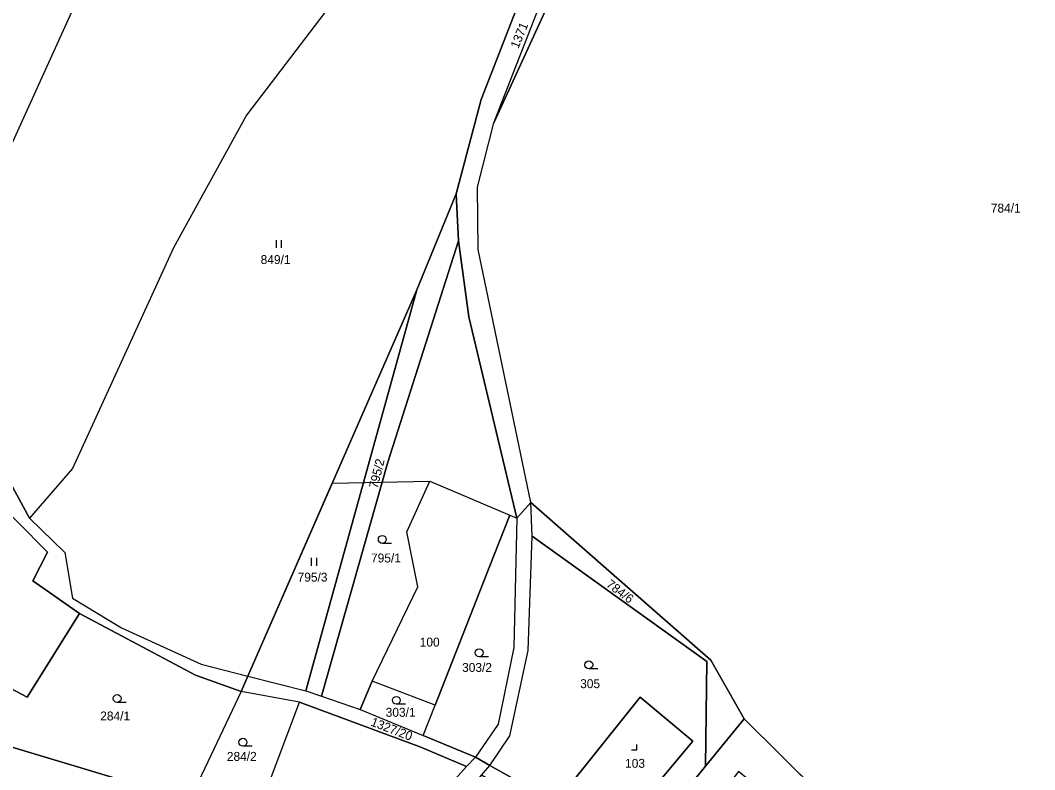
# Model space of a CAD drawing. Extents: x -588699 to -585793, y -1060280 to -1056731.
# Drawn here: x -587576 to -587382.9, y -1058239.7 to -1058097.1 of the extents above; entities that cross this region are included whole.
import ezdxf

# ---------------------------------------------------------------- set-up
doc = ezdxf.new("R2010")
doc.units = 0
for name, color, linetype in [('Druh pozemku', 7, 'Continuous'), ('Lesy', 7, 'Continuous'), ('Parcela nároku', 7, 'Continuous'), ('Vnější obvod_k šeření', 7, 'Continuous')]:
    doc.layers.add(name, color=color, linetype=linetype)

msp = doc.modelspace()

# ---------------------------------------------------------------- linework, layer by layer
at = {"layer": 'Druh pozemku'}
for p, q in [((-587527.32, -1058138.93), (-587527.32, -1058140.43)), ((-587526.3, -1058140.43), (-587526.3, -1058138.93)), ((-587505.34, -1058196.66), (-587507.09, -1058196.66)), ((-587520.6, -1058199.42), (-587520.6, -1058200.92)), ((-587519.58, -1058200.92), (-587519.58, -1058199.42)), ((-587486.89, -1058218.23), (-587488.64, -1058218.23)), ((-587466.02, -1058220.53), (-587467.77, -1058220.53)), ((-587555.83, -1058226.93), (-587557.58, -1058226.93)), ((-587502.67, -1058227.28), (-587504.42, -1058227.28)), ((-587531.88, -1058235.26), (-587533.63, -1058235.26))]:
    msp.add_line(p, q, dxfattribs=at)
msp.add_lwpolyline([(-587459.64, -1058235.92), (-587458.64, -1058235.92), (-587458.64, -1058234.92)], dxfattribs=at)
for centre in [(-587507.09, -1058195.91), (-587488.64, -1058217.48), (-587467.77, -1058219.78), (-587557.58, -1058226.18), (-587504.42, -1058226.53), (-587533.63, -1058234.51)]:
    msp.add_circle(centre, 0.75, dxfattribs=at)
at = {"layer": 'Lesy'}
for p, q in [((-587532.69, -1058221.91), (-587516.61, -1058185.17)), ((-587516.61, -1058185.17), (-587498.02, -1058184.82)), ((-587516.61, -1058185.17), (-587516.61, -1058185.17)), ((-587516.61, -1058185.17), (-587516.61, -1058185.17)), ((-587498.02, -1058184.82), (-587482.8, -1058191.31)), ((-587481.48, -1058191.87), (-587478.83, -1058188.89)), ((-587478.83, -1058188.89), (-587444.54, -1058218.88)), ((-587482.8, -1058191.31), (-587481.48, -1058191.87)), ((-587576.63, -1058192.51), (-587570.81, -1058198.31)), ((-587570.81, -1058198.31), (-587573.61, -1058203.8)), ((-587573.61, -1058203.8), (-587564.72, -1058210.02)), ((-587564.72, -1058210.02), (-587542.68, -1058221.73)), ((-587444.54, -1058218.88), (-587438.17, -1058230.02)), ((-587542.68, -1058221.73), (-587533.98, -1058224.84)), ((-587533.98, -1058224.84), (-587532.69, -1058221.91)), ((-587438.17, -1058230.02), (-587409.09, -1058258.83))]:
    msp.add_line(p, q, dxfattribs=at)
at = {"layer": 'Parcela nároku'}
for points in [[(-587527.58, -1058033.11), (-587512.43, -1058021.56), (-587484.15, -1058010.09), (-587474.8, -1058004.29), (-587465.82, -1058059.86), (-587503.14, -1058076.04), (-587532.94, -1058115.16), (-587546.85, -1058140.39), (-587566.06, -1058182.4), (-587574.29, -1058191.87), (-587590.81, -1058161.45), (-587593.08, -1058145.43), (-587589.69, -1058125.26), (-587570.64, -1058078.67), (-587551.05, -1058065.74), (-587538.76, -1058045.77)], [(-587345.44, -1058028.92), (-587320.47, -1058029.95), (-587326.37, -1058086.73), (-587339.42, -1058135.2), (-587351.4, -1058206.3), (-587377.92, -1058277.75), (-587409.09, -1058258.83), (-587438.17, -1058230.02), (-587444.54, -1058218.88), (-587478.83, -1058188.89), (-587488.81, -1058140.74), (-587488.94, -1058128.88), (-587485.87, -1058116.62), (-587469.24, -1058080.38), (-587460.27, -1058069.38), (-587445.31, -1058054.69), (-587393.66, -1058044.61), (-587379.52, -1058038.97), (-587353.28, -1058031.95)], [(-587472.47, -1058082.32), (-587463.05, -1058066.61), (-587456.91, -1058059.97), (-587445.31, -1058054.69), (-587460.27, -1058069.38), (-587469.24, -1058080.38), (-587485.87, -1058116.62)], [(-587546.85, -1058140.39), (-587566.06, -1058182.4), (-587574.29, -1058191.87), (-587567.55, -1058198.39), (-587566.06, -1058207.06), (-587556.73, -1058212.76), (-587541.57, -1058219.62), (-587532.69, -1058221.91), (-587500.54, -1058148.42), (-587493.05, -1058130.11), (-587488.27, -1058112.18), (-587475.92, -1058080.51), (-587464.99, -1058063.65), (-587465.82, -1058059.86), (-587503.14, -1058076.04), (-587532.94, -1058115.16)], [(-587488.27, -1058112.18), (-587493.05, -1058130.11), (-587492.55, -1058139.05), (-587490.61, -1058153.54), (-587481.48, -1058191.87), (-587482.06, -1058216.46), (-587485.02, -1058231.04), (-587489.32, -1058237.37), (-587486.6, -1058238.91), (-587482.8, -1058233.27), (-587479.34, -1058217.02), (-587478.55, -1058195.26), (-587478.83, -1058188.89), (-587488.81, -1058140.74), (-587488.94, -1058128.88), (-587485.87, -1058116.62), (-587472.47, -1058082.32), (-587463.05, -1058066.61), (-587456.91, -1058059.97), (-587464.99, -1058063.65), (-587475.92, -1058080.51)], [(-587493.05, -1058130.11), (-587500.54, -1058148.42), (-587521.67, -1058224.75), (-587518.67, -1058225.76), (-587506.06, -1058181.19), (-587492.55, -1058139.05)], [(-587490.61, -1058153.54), (-587492.55, -1058139.05), (-587506.06, -1058181.19), (-587518.67, -1058225.76), (-587511.28, -1058228.3), (-587509.02, -1058222.9), (-587500.32, -1058204.9), (-587502.39, -1058194.46), (-587498.02, -1058184.82), (-587482.8, -1058191.31), (-587481.48, -1058191.87)], [(-587500.54, -1058148.42), (-587532.69, -1058221.91), (-587521.67, -1058224.75)], [(-587613.49, -1058209.28), (-587594.49, -1058181.8), (-587592.95, -1058183.93), (-587589.15, -1058186.74), (-587582.84, -1058191.41), (-587580.71, -1058188.44), (-587576.63, -1058192.51), (-587570.81, -1058198.31), (-587573.61, -1058203.8), (-587564.72, -1058210.02), (-587574.71, -1058225.95), (-587584.71, -1058220.65), (-587580.51, -1058214.58), (-587588.96, -1058208.27), (-587593.11, -1058213.84), (-587596.84, -1058210.95), (-587597.22, -1058210.65), (-587606.24, -1058203.65)], [(-587498.02, -1058184.82), (-587482.8, -1058191.31), (-587486.72, -1058201.25), (-587489.71, -1058208.84), (-587497.04, -1058227.45), (-587509.02, -1058222.9), (-587500.32, -1058204.9), (-587502.39, -1058194.46)], [(-587445.52, -1058239.05), (-587445.31, -1058219.16), (-587478.55, -1058195.26), (-587478.83, -1058188.89), (-587444.54, -1058218.88), (-587438.17, -1058230.02)], [(-587489.71, -1058208.84), (-587486.72, -1058201.25), (-587482.8, -1058191.31), (-587481.48, -1058191.87), (-587482.06, -1058216.46), (-587485.02, -1058231.04), (-587489.32, -1058237.37), (-587499.32, -1058233.23), (-587497.04, -1058227.45)], [(-587486.6, -1058238.91), (-587482.8, -1058233.27), (-587479.34, -1058217.02), (-587478.55, -1058195.26), (-587445.31, -1058219.16), (-587445.52, -1058239.05), (-587458.33, -1058254.77)], [(-587564.72, -1058210.02), (-587542.68, -1058221.73), (-587533.98, -1058224.84), (-587543.81, -1058245.62), (-587594.11, -1058230.47), (-587604.18, -1058226.81), (-587600.44, -1058221.67), (-587594.99, -1058216.36), (-587586.42, -1058223.13), (-587584.71, -1058220.65), (-587574.71, -1058225.95)], [(-587499.32, -1058233.23), (-587489.32, -1058237.37), (-587491.04, -1058239.13), (-587499.77, -1058235.44), (-587522.86, -1058226.86), (-587533.98, -1058224.84), (-587532.69, -1058221.91), (-587521.67, -1058224.75), (-587518.67, -1058225.76), (-587511.28, -1058228.3)], [(-587509.02, -1058222.9), (-587511.28, -1058228.3), (-587499.32, -1058233.23), (-587497.04, -1058227.45)], [(-587522.86, -1058226.86), (-587533.98, -1058224.84), (-587543.81, -1058245.62), (-587531.58, -1058249.98)], [(-587457.98, -1058225.94), (-587470.2, -1058241.13), (-587459.27, -1058251.43), (-587454.05, -1058245.1), (-587455.68, -1058243.56), (-587447.93, -1058234.31)], [(-587447.93, -1058234.31), (-587455.68, -1058243.56), (-587454.05, -1058245.1), (-587459.27, -1058251.43), (-587470.2, -1058241.13), (-587457.98, -1058225.94)], [(-587522.86, -1058226.86), (-587499.77, -1058235.44), (-587491.04, -1058239.13), (-587511.42, -1058261.89), (-587520.95, -1058253.77), (-587531.58, -1058249.98)], [(-587438.17, -1058230.02), (-587409.09, -1058258.83), (-587377.92, -1058277.75), (-587379.39, -1058282.93), (-587379.69, -1058284.16), (-587380.64, -1058288.11), (-587382.51, -1058301.76), (-587401.12, -1058288.15), (-587430.44, -1058266.69), (-587421.74, -1058254.37), (-587439.28, -1058240.07), (-587475.39, -1058286.82), (-587481.24, -1058282.88), (-587459.91, -1058256.7), (-587458.33, -1058254.77), (-587445.52, -1058239.05)], [(-587491.04, -1058239.13), (-587511.42, -1058261.89), (-587508.12, -1058264.7), (-587488.17, -1058240.8), (-587486.6, -1058238.91), (-587489.32, -1058237.37)], [(-587486.6, -1058238.91), (-587458.33, -1058254.77), (-587459.91, -1058256.7), (-587464.95, -1058253.95), (-587474.34, -1058248.83), (-587488.17, -1058240.8)]]:
    msp.add_lwpolyline(points, close=True, dxfattribs=at)
for points in [[(-587590.81, -1058161.45), (-587574.29, -1058191.87), (-587567.55, -1058198.39), (-587566.06, -1058207.06), (-587556.73, -1058212.76), (-587541.57, -1058219.62), (-587532.69, -1058221.91), (-587533.98, -1058224.84), (-587542.68, -1058221.73), (-587564.72, -1058210.02), (-587573.61, -1058203.8), (-587570.81, -1058198.31), (-587576.63, -1058192.51)], [(-587594.11, -1058230.47), (-587543.81, -1058245.62), (-587531.58, -1058249.98), (-587520.95, -1058253.77), (-587511.42, -1058261.89), (-587508.12, -1058264.7), (-587485.12, -1058280.26), (-587481.24, -1058282.88), (-587475.39, -1058286.82), (-587460.81, -1058295.62), (-587444.42, -1058308.21), (-587441.79, -1058310.38), (-587431.23, -1058319.09), (-587428.47, -1058321.37), (-587427.8, -1058324.05), (-587426.31, -1058328.62), (-587418.44, -1058335.18), (-587402.65, -1058360.88), (-587397.44, -1058368.8)]]:
    msp.add_lwpolyline(points, dxfattribs=at)
at = {"layer": 'Vnější obvod_k šeření'}
msp.add_lwpolyline([(-587598.78, -1058147.31), (-587587.54, -1058137.18), (-587578.39, -1058122.34), (-587562.78, -1058087.91), (-587557.09, -1058081.9), (-587547.48, -1058078.1), (-587531.42, -1058078.42), (-587519.59, -1058074.95), (-587509.13, -1058065.73), (-587501.68, -1058061.09), (-587491.48, -1058057.56), (-587477.36, -1058055.8), (-587461.22, -1058052.2), (-587453.76, -1058048.47), (-587450.1, -1058043.17), (-587447.95, -1058035.13), (-587445.79, -1058031.73), (-587382.9, -1058022.25), (-587318.71, -1058013.6), (-587259.11, -1057994.38), (-587212.43, -1057983.28), (-587175.02, -1057974.24), (-587119.54, -1057948.26)], dxfattribs=at)

# ---------------------------------------------------------------- texts
at = {"layer": 'Parcela nároku'}
for s, rotation, p in [('1371', 67.5769, (-587481.19, -1058102.62)), ('795/2', 76.0859, (-587507.99, -1058186.33)), ('784/6', 322.9221, (-587464.59, -1058204.75)), ('1327/20', 338.9287, (-587509.43, -1058231.3))]:
    msp.add_text(s, height=1.7, rotation=rotation, dxfattribs=at).set_placement(p)
for s, p in [('784/1', (-587391.22, -1058133.7)), ('849/1', (-587530.25, -1058143.5)), ('795/1', (-587509.23, -1058200.29)), ('795/3', (-587523.21, -1058203.94)), ('100', (-587499.96, -1058216.3)), ('303/2', (-587491.89, -1058221.12)), ('305', (-587469.41, -1058224.21)), ('303/1', (-587506.44, -1058229.66)), ('284/1', (-587560.8, -1058230.36)), ('284/2', (-587536.69, -1058238.05)), ('103', (-587460.86, -1058239.37))]:
    msp.add_text(s, height=1.7, dxfattribs=at).set_placement(p)

doc.saveas('drawing.dxf')
